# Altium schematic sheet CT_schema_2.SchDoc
size 276 x 169 mm
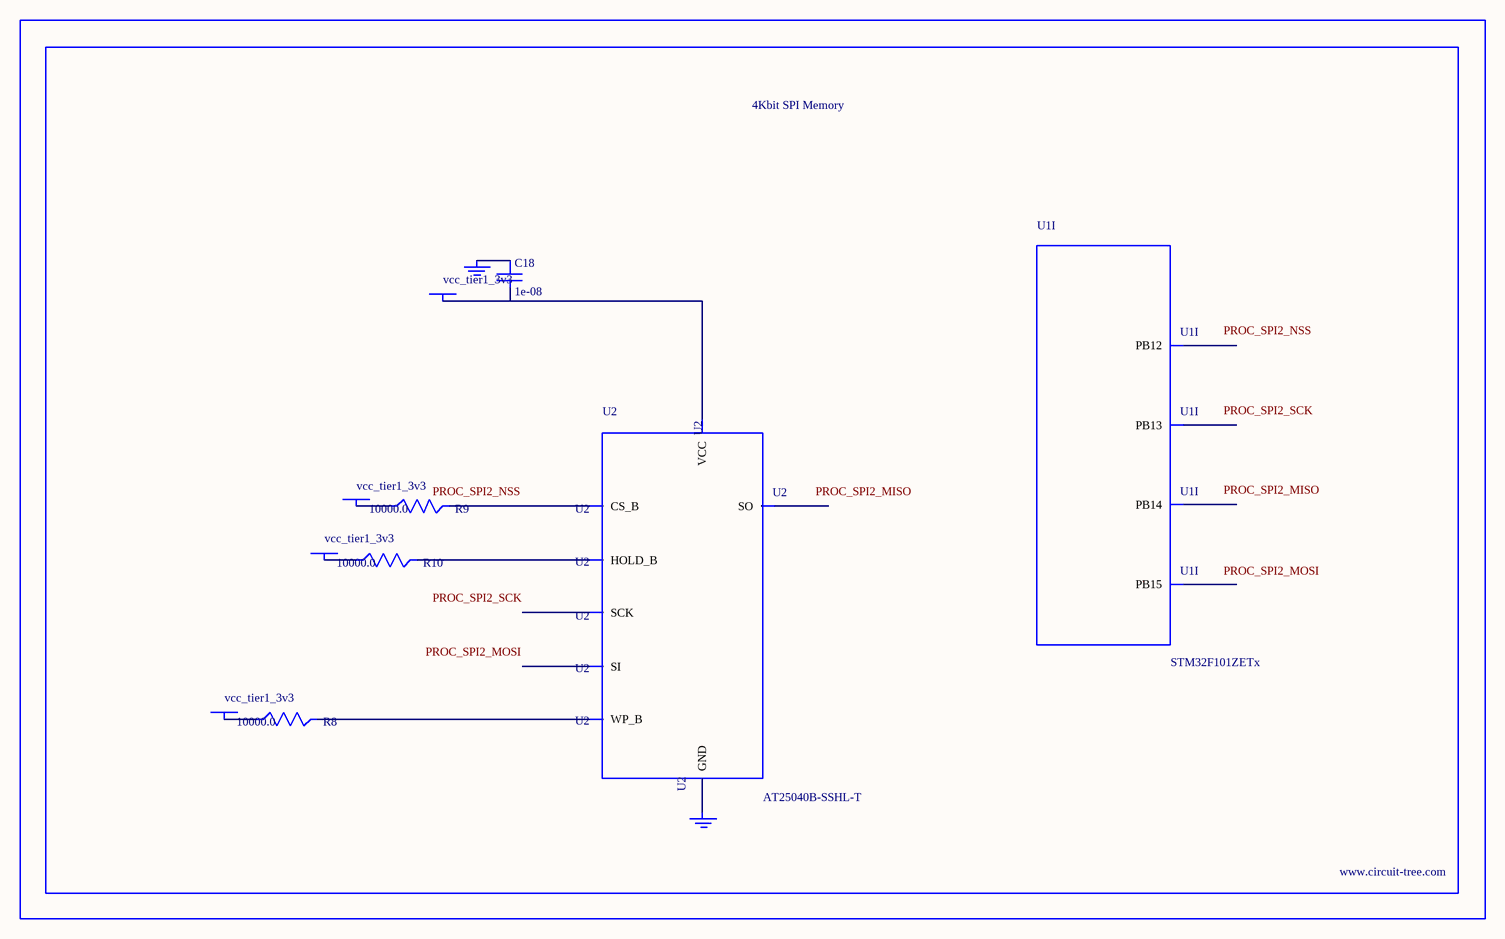
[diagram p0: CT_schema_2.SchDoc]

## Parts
BORDER1  (no value)
C18  1e-08  [C0402]
GND_INSTANCE_1_0  (no value)
GND_INSTANCE_1_1  (no value)
POWER_INSTANCE_1_0  vcc_tier1_3v3
POWER_INSTANCE_1_1  vcc_tier1_3v3
POWER_INSTANCE_1_2  vcc_tier1_3v3
POWER_INSTANCE_1_3  vcc_tier1_3v3
R8  10000.0  [R0603]
R9  10000.0  [R0603]
R10  10000.0  [R0603]
U1  STM32F101ZETx  [LQFP144]  (part I of 12)
U2  AT25040B-SSHL-T  [SOIC-8]

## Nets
NetC18_1: C18.1 GND_INSTANCE_1_0.0(GND)
NetC18_2: C18.2 POWER_INSTANCE_1_3.0(PWR) U2.8(VCC)
NetGND_INSTANCE_1_1_0: GND_INSTANCE_1_1.0(GND) U2.4(GND)
NetPOWER_INSTANCE_1_0_0: POWER_INSTANCE_1_0.0(PWR) R9.1
NetPOWER_INSTANCE_1_1_0: POWER_INSTANCE_1_1.0(PWR) R8.1
NetPOWER_INSTANCE_1_2_0: POWER_INSTANCE_1_2.0(PWR) R10.1
NetR8_2: R8.2 U2.3(WP_B)
NetR9_2: R9.2 U2.1(CS_B)
NetR10_2: R10.2 U2.7(HOLD_B)

Not connected (* = marked no-connect by the designer): U1 73(PB12) 74(PB13) 75(PB14) 76(PB15); U2 2(SO) 5(SI) 6(SCK)

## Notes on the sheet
- Labels drawn without touching a wire or pin: PROC_SPI2_MISO, PROC_SPI2_MOSI, PROC_SPI2_NSS, PROC_SPI2_SCK

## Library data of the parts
BORDER1 = BORDER_PAGE1
C18 = C0402C103K3RAC
GND_INSTANCE_1_0 GND_INSTANCE_1_1 = GND
POWER_INSTANCE_1_0-POWER_INSTANCE_1_3 = PWR
R8-R10 = RC0603JR-0710KL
